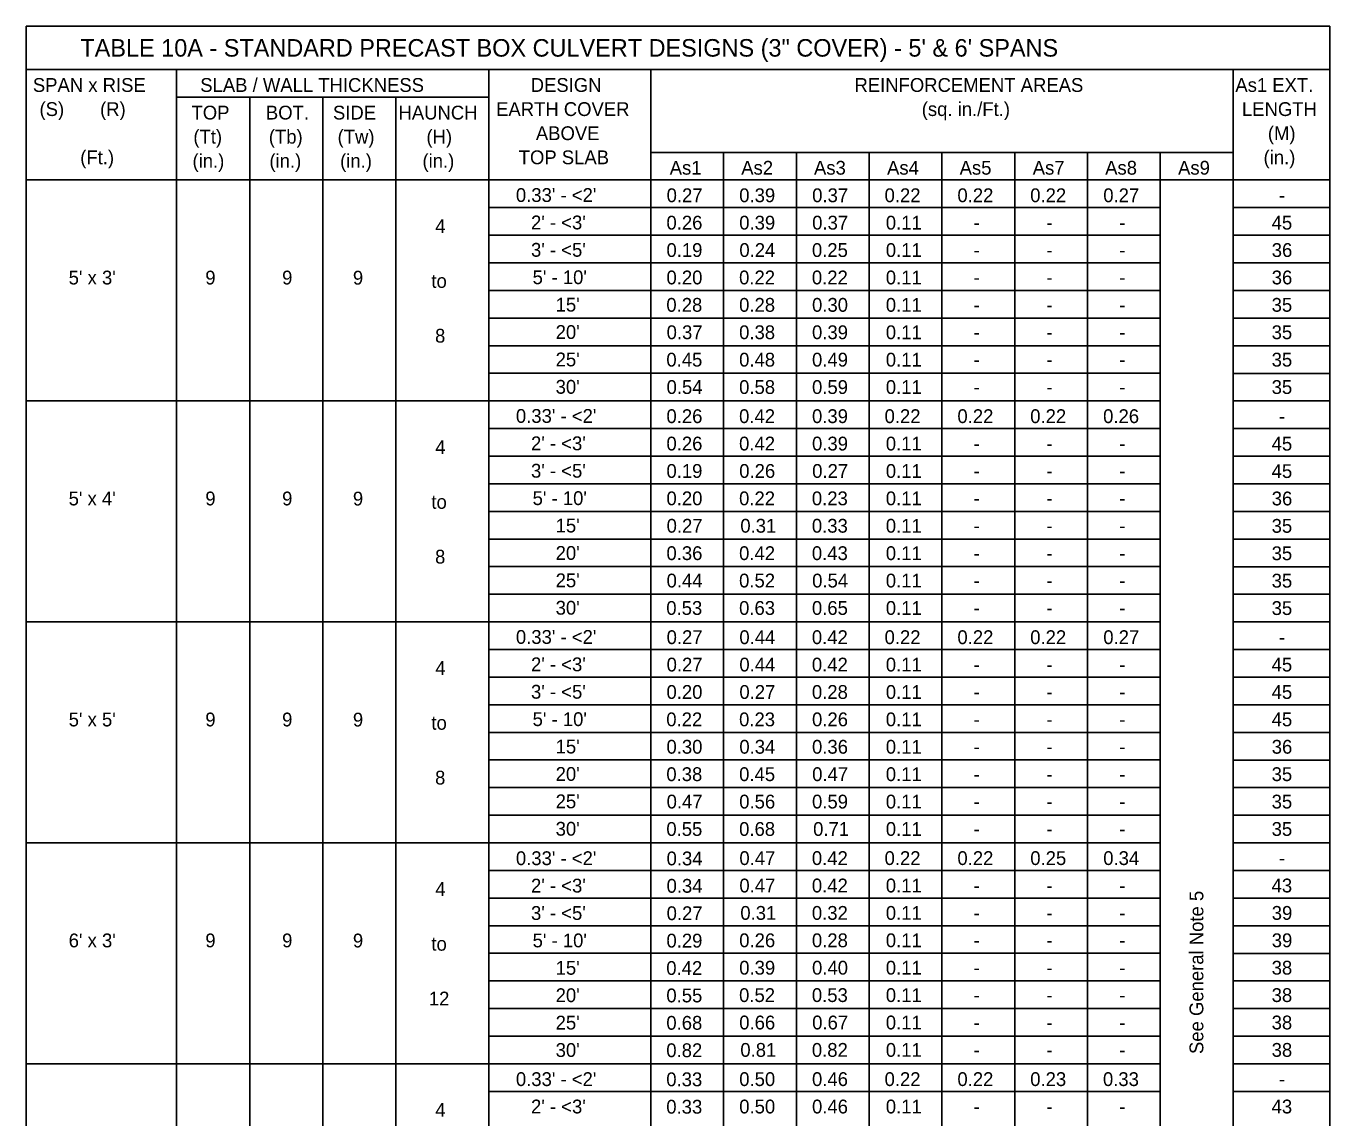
# Model space of a CAD drawing. Extents: x 10338.56 to 10340.78, y 76371.55 to 76372.62.
# Drawn here: x 10338.57 to 10339.164, y 76372.037 to 76372.535 of the extents above; entities that cross this region are included whole.
import ezdxf

# ---------------------------------------------------------------- set-up
doc = ezdxf.new("R2010")
doc.units = 0
doc.layers.add('AdhocPoint_dp', color=7, linetype='Continuous')
doc.layers.add('PlotBorder_dp', color=7, linetype='Continuous')

msp = doc.modelspace()

# ---------------------------------------------------------------- linework, layer by layer
at = {"layer": 'PlotBorder_dp'}
for p, q in [((10338.5697, 76372.53475), (10338.5697, 76371.75893)), ((10338.5697, 76372.53475), (10339.16444, 76372.53475)), ((10339.16444, 76372.53475), (10339.16444, 76371.75893)), ((10338.5697, 76372.51488), (10339.16444, 76372.51488)), ((10338.63833, 76372.51488), (10338.63833, 76371.75893)), ((10338.78078, 76372.51488), (10338.78078, 76371.75893)), ((10338.85466, 76372.51488), (10338.85466, 76371.75893)), ((10339.12025, 76372.51488), (10339.12025, 76371.75893)), ((10338.63833, 76372.50228), (10338.78078, 76372.50228)), ((10338.67169, 76372.50228), (10338.67169, 76371.75893)), ((10338.70506, 76372.50228), (10338.70506, 76371.75893)), ((10338.73842, 76372.50228), (10338.73842, 76371.75893)), ((10338.85466, 76372.47713), (10339.12025, 76372.47713)), ((10338.88786, 76372.47713), (10338.88786, 76371.75893)), ((10338.92106, 76372.47713), (10338.92106, 76371.75893)), ((10338.95425, 76372.47713), (10338.95425, 76371.75893)), ((10338.98745, 76372.47713), (10338.98745, 76371.75893)), ((10339.02065, 76372.47713), (10339.02065, 76371.75893)), ((10339.02065, 76372.47713), (10339.02065, 76371.75893)), ((10339.05385, 76372.47713), (10339.05385, 76371.75893)), ((10339.08705, 76372.47713), (10339.08705, 76371.75893)), ((10338.5697, 76372.46453), (10339.16444, 76372.46453)), ((10338.78078, 76372.45193), (10339.08705, 76372.45193)), ((10339.12025, 76372.45191), (10339.16444, 76372.45191)), ((10338.78078, 76372.43933), (10339.08705, 76372.43933)), ((10339.12025, 76372.43931), (10339.16444, 76372.43931)), ((10338.78078, 76372.42673), (10339.08705, 76372.42673)), ((10339.12025, 76372.42671), (10339.16444, 76372.42671)), ((10338.78078, 76372.41413), (10339.08705, 76372.41413)), ((10339.12025, 76372.41411), (10339.16444, 76372.41411)), ((10338.78078, 76372.40153), (10339.08705, 76372.40153)), ((10339.12025, 76372.40151), (10339.16444, 76372.40151)), ((10338.78078, 76372.38893), (10339.08705, 76372.38893)), ((10339.12025, 76372.38891), (10339.16444, 76372.38891)), ((10338.78078, 76372.37633), (10339.08705, 76372.37633)), ((10339.12025, 76372.37631), (10339.16444, 76372.37631)), ((10338.5697, 76372.36373), (10339.08705, 76372.36373)), ((10339.12025, 76372.36371), (10339.16444, 76372.36371)), ((10338.78078, 76372.35113), (10339.08705, 76372.35113)), ((10339.12025, 76372.35111), (10339.16444, 76372.35111)), ((10338.78078, 76372.33853), (10339.08705, 76372.33853)), ((10339.12025, 76372.33851), (10339.16444, 76372.33851)), ((10338.78078, 76372.32593), (10339.08705, 76372.32593)), ((10339.12025, 76372.32591), (10339.16444, 76372.32591)), ((10338.78078, 76372.31333), (10339.08705, 76372.31333)), ((10339.12025, 76372.31331), (10339.16444, 76372.31331)), ((10338.78078, 76372.30073), (10339.08705, 76372.30073)), ((10339.12025, 76372.30071), (10339.16444, 76372.30071)), ((10338.78078, 76372.28813), (10339.08705, 76372.28813)), ((10339.12025, 76372.28811), (10339.16444, 76372.28811)), ((10338.78078, 76372.27553), (10339.08705, 76372.27553)), ((10339.12025, 76372.27551), (10339.16444, 76372.27551)), ((10338.5697, 76372.26293), (10339.08705, 76372.26293)), ((10339.12025, 76372.26291), (10339.16444, 76372.26291)), ((10338.78078, 76372.25033), (10339.08705, 76372.25033)), ((10339.12025, 76372.25031), (10339.16444, 76372.25031)), ((10338.78078, 76372.23773), (10339.08705, 76372.23773)), ((10339.12025, 76372.23771), (10339.16444, 76372.23771)), ((10338.78078, 76372.22513), (10339.08705, 76372.22513)), ((10339.12025, 76372.22511), (10339.16444, 76372.22511)), ((10338.78078, 76372.21253), (10339.08705, 76372.21253)), ((10339.12025, 76372.21251), (10339.16444, 76372.21251)), ((10338.78078, 76372.19993), (10339.08705, 76372.19993)), ((10339.12025, 76372.19991), (10339.16444, 76372.19991)), ((10338.78078, 76372.18733), (10339.08705, 76372.18733)), ((10339.12025, 76372.18731), (10339.16444, 76372.18731)), ((10338.78078, 76372.17473), (10339.08705, 76372.17473)), ((10339.12025, 76372.17471), (10339.16444, 76372.17471)), ((10338.5697, 76372.16213), (10339.08705, 76372.16213)), ((10339.12025, 76372.16211), (10339.16444, 76372.16211)), ((10338.78078, 76372.14953), (10339.08705, 76372.14953)), ((10339.12025, 76372.14951), (10339.16444, 76372.14951)), ((10338.78078, 76372.13693), (10339.08705, 76372.13693)), ((10339.12025, 76372.13691), (10339.16444, 76372.13691)), ((10338.78078, 76372.12433), (10339.08705, 76372.12433)), ((10339.12025, 76372.12431), (10339.16444, 76372.12431)), ((10338.78078, 76372.11173), (10339.08705, 76372.11173)), ((10339.12025, 76372.11171), (10339.16444, 76372.11171)), ((10338.78078, 76372.09913), (10339.08705, 76372.09913)), ((10339.12025, 76372.09911), (10339.16444, 76372.09911)), ((10338.78078, 76372.08653), (10339.08705, 76372.08653)), ((10339.12025, 76372.08651), (10339.16444, 76372.08651)), ((10338.78078, 76372.07393), (10339.08705, 76372.07393)), ((10339.12025, 76372.07391), (10339.16444, 76372.07391)), ((10338.5697, 76372.06133), (10339.08705, 76372.06133)), ((10338.78139, 76372.06131), (10338.85356, 76372.06131)), ((10339.12025, 76372.06131), (10339.16444, 76372.06131)), ((10338.78078, 76372.04873), (10339.08705, 76372.04873)), ((10339.12025, 76372.04871), (10339.16444, 76372.04871))]:
    msp.add_line(p, q, dxfattribs=at)

# ---------------------------------------------------------------- texts
at = {"layer": 'AdhocPoint_dp'}
for s, height, p in [('TABLE 10A - STANDARD PRECAST BOX CULVERT DESIGNS (3" COVER) - 5\' & 6\' SPANS', 0.008, (10338.59446, 76372.52081)), ('SLAB / WALL THICKNESS', 0.0063, (10338.64915, 76372.50472)), ('As1', 0.0063, (10338.86328, 76372.46696)), ('As2', 0.0063, (10338.89591, 76372.46696)), ('As3', 0.0063, (10338.9291, 76372.46696)), ('As4', 0.0063, (10338.96243, 76372.46696)), ('As5', 0.0063, (10338.99553, 76372.46696)), ('As7', 0.0063, (10339.02887, 76372.46696)), ('As8', 0.0063, (10339.06192, 76372.46696)), ('As9', 0.0063, (10339.09517, 76372.46696)), ("5' x 3'", 0.0063, (10338.58912, 76372.41686)), ('9', 0.0063, (10338.65145, 76372.41686)), ('9', 0.0063, (10338.68649, 76372.41686)), ('9', 0.0063, (10338.71878, 76372.4168)), ("5' x 4'", 0.0063, (10338.58911, 76372.31607)), ('9', 0.0063, (10338.65145, 76372.31607)), ('9', 0.0063, (10338.68649, 76372.31607)), ('9', 0.0063, (10338.71878, 76372.31602)), ("5' x 5'", 0.0063, (10338.58913, 76372.21524)), ('9', 0.0063, (10338.65145, 76372.21524)), ('9', 0.0063, (10338.68649, 76372.21524)), ('9', 0.0063, (10338.71878, 76372.21519)), ('9', 0.0063, (10338.65145, 76372.11446)), ('9', 0.0063, (10338.68649, 76372.11446)), ('9', 0.0063, (10338.71878, 76372.11441))]:
    msp.add_text(s, height=height, dxfattribs=at).set_placement(p)
msp.add_text('See General Note 5', height=0.0063, rotation=90, dxfattribs=at).set_placement((10339.1067, 76372.06579))
at = {"layer": 'PlotBorder_dp'}
for s, p in [('SPAN x RISE', (10338.57279, 76372.50472)), ('DESIGN', (10338.79988, 76372.50472)), ('REINFORCEMENT AREAS', (10338.94756, 76372.50472)), ('(S)       (R)', (10338.57583, 76372.49372)), ('TOP', (10338.64516, 76372.49212)), ('BOT.', (10338.67909, 76372.49212)), ('SIDE', (10338.70968, 76372.49212)), ('HAUNCH', (10338.73958, 76372.49212)), ('EARTH COVER', (10338.78409, 76372.49372)), ('(sq. in./Ft.)', (10338.97825, 76372.49372)), ('ABOVE', (10338.80223, 76372.48272)), ('(Tt)', (10338.646, 76372.48112)), ('(Tb)', (10338.68043, 76372.48112)), ('(Tw)', (10338.71179, 76372.48112)), ('(H)', (10338.75232, 76372.48112)), ('(Ft.)', (10338.5944, 76372.47172)), ('(in.)', (10338.64561, 76372.47012)), ('(in.)', (10338.6807, 76372.47012)), ('(in.)', (10338.71294, 76372.47012)), ('(in.)', (10338.75051, 76372.47012)), ('TOP SLAB', (10338.7944, 76372.47172)), ("0.33' - <2'", (10338.79313, 76372.45451)), ('0.27', (10338.86188, 76372.45441)), ('0.39', (10338.895, 76372.45441)), ('0.37', (10338.92827, 76372.45441)), ('0.22', (10338.96129, 76372.45441)), ('0.22', (10338.99452, 76372.45441)), ('0.22', (10339.02773, 76372.45441)), ('0.27', (10339.06106, 76372.45441)), ('-', (10339.14117, 76372.45441)), ("2' - <3'", (10338.80003, 76372.44201)), ('0.26', (10338.8618, 76372.44191)), ('0.39', (10338.895, 76372.44191)), ('0.37', (10338.92827, 76372.44191)), ('0.11', (10338.96186, 76372.44191)), ('45', (10339.13786, 76372.44191)), ('4', (10338.75636, 76372.44033)), ('-', (10339.00192, 76372.44191)), ('-', (10339.03513, 76372.44191)), ('-', (10339.06832, 76372.44191)), ("3' - <5'", (10338.80003, 76372.42951)), ('0.19', (10338.8618, 76372.42941)), ('0.24', (10338.89506, 76372.42941)), ('0.25', (10338.92816, 76372.42941)), ('0.11', (10338.96186, 76372.42941)), ('36', (10339.1379, 76372.42941)), ('-', (10339.00192, 76372.42941)), ('-', (10339.03513, 76372.42941)), ('-', (10339.06832, 76372.42941)), ("5' - 10'", (10338.80075, 76372.41701)), ('0.20', (10338.86181, 76372.41691)), ('0.22', (10338.89493, 76372.41691)), ('0.22', (10338.92813, 76372.41691)), ('0.11', (10338.96186, 76372.41691)), ('36', (10339.1379, 76372.41691)), ('to', (10338.75458, 76372.41533)), ('-', (10339.00192, 76372.41691)), ('-', (10339.03513, 76372.41691)), ('-', (10339.06832, 76372.41691)), ("15'", (10338.81126, 76372.40451)), ('0.28', (10338.86175, 76372.40441)), ('0.28', (10338.89495, 76372.40441)), ('0.30', (10338.92821, 76372.40441)), ('0.11', (10338.96186, 76372.40441)), ('-', (10339.00192, 76372.40441)), ('-', (10339.03513, 76372.40441)), ('-', (10339.06832, 76372.40441)), ('35', (10339.13786, 76372.40441)), ('8', (10338.75625, 76372.39033)), ("20'", (10338.81126, 76372.39201)), ('0.37', (10338.86188, 76372.39191)), ('0.38', (10338.89495, 76372.39191)), ('0.39', (10338.9282, 76372.39191)), ('0.11', (10338.96186, 76372.39191)), ('-', (10339.00192, 76372.39191)), ('-', (10339.03513, 76372.39191)), ('-', (10339.06832, 76372.39191)), ('35', (10339.13786, 76372.39191)), ("25'", (10338.81126, 76372.37951)), ('0.45', (10338.86176, 76372.37941)), ('0.48', (10338.89495, 76372.37941)), ('0.49', (10338.9282, 76372.37941)), ('0.11', (10338.96186, 76372.37941)), ('-', (10339.00192, 76372.37941)), ('-', (10339.03513, 76372.37941)), ('-', (10339.06832, 76372.37941)), ('35', (10339.13786, 76372.37941)), ("30'", (10338.81126, 76372.36701)), ('0.54', (10338.86186, 76372.36691)), ('0.58', (10338.89495, 76372.36691)), ('0.59', (10338.9282, 76372.36691)), ('0.11', (10338.96186, 76372.36691)), ('-', (10339.00192, 76372.36691)), ('-', (10339.03513, 76372.36691)), ('-', (10339.06832, 76372.36691)), ('35', (10339.13786, 76372.36691)), ("0.33' - <2'", (10338.79313, 76372.35373)), ('0.26', (10338.8618, 76372.35363)), ('0.42', (10338.89493, 76372.35363)), ('0.39', (10338.9282, 76372.35363)), ('0.22', (10338.96129, 76372.35363)), ('0.22', (10338.99452, 76372.35363)), ('0.22', (10339.02773, 76372.35363)), ('0.26', (10339.06098, 76372.35363)), ('-', (10339.14117, 76372.35358)), ("2' - <3'", (10338.80003, 76372.34123)), ('0.26', (10338.8618, 76372.34113)), ('0.42', (10338.89493, 76372.34113)), ('0.39', (10338.9282, 76372.34113)), ('0.11', (10338.96186, 76372.34113)), ('45', (10339.13786, 76372.34108)), ('4', (10338.75636, 76372.33953)), ('-', (10339.00192, 76372.34113)), ('-', (10339.03513, 76372.34113)), ('-', (10339.06832, 76372.34113)), ("3' - <5'", (10338.80003, 76372.32873)), ('0.19', (10338.8618, 76372.32863)), ('0.26', (10338.895, 76372.32863)), ('0.27', (10338.92827, 76372.32863)), ('0.11', (10338.96186, 76372.32863)), ('45', (10339.13786, 76372.32858)), ('-', (10339.00192, 76372.32863)), ('-', (10339.03513, 76372.32863)), ('-', (10339.06832, 76372.32863)), ("5' - 10'", (10338.80075, 76372.31623)), ('0.20', (10338.86181, 76372.31613)), ('0.22', (10338.89493, 76372.31613)), ('0.23', (10338.92813, 76372.31613)), ('0.11', (10338.96186, 76372.31613)), ('36', (10339.1379, 76372.31608)), ('to', (10338.75458, 76372.31453)), ('-', (10339.00192, 76372.31613)), ('-', (10339.03513, 76372.31613)), ('-', (10339.06832, 76372.31613)), ("15'", (10338.81126, 76372.30373)), ('0.27', (10338.86188, 76372.30363)), ('0.31', (10338.8955, 76372.30363)), ('0.33', (10338.92813, 76372.30363)), ('0.11', (10338.96186, 76372.30363)), ('-', (10339.00192, 76372.30363)), ('-', (10339.03513, 76372.30363)), ('-', (10339.06832, 76372.30363)), ('35', (10339.13786, 76372.30358)), ('8', (10338.75625, 76372.28953)), ("20'", (10338.81126, 76372.29123)), ('0.36', (10338.8618, 76372.29113)), ('0.42', (10338.89493, 76372.29113)), ('0.43', (10338.92813, 76372.29113)), ('0.11', (10338.96186, 76372.29113)), ('-', (10339.00192, 76372.29113)), ('-', (10339.03513, 76372.29113)), ('-', (10339.06832, 76372.29113)), ('35', (10339.13786, 76372.29108)), ("25'", (10338.81126, 76372.27873)), ('0.44', (10338.86186, 76372.27863)), ('0.52', (10338.89493, 76372.27863)), ('0.54', (10338.92826, 76372.27863)), ('0.11', (10338.96186, 76372.27863)), ('-', (10339.00192, 76372.27863)), ('-', (10339.03513, 76372.27863)), ('-', (10339.06832, 76372.27863)), ('35', (10339.13786, 76372.27858)), ("30'", (10338.81126, 76372.26623)), ('0.53', (10338.86173, 76372.26613)), ('0.63', (10338.89493, 76372.26613)), ('0.65', (10338.92816, 76372.26613)), ('0.11', (10338.96186, 76372.26613)), ('-', (10339.00192, 76372.26613)), ('-', (10339.03513, 76372.26613)), ('-', (10339.06832, 76372.26613)), ('35', (10339.13786, 76372.26608)), ("0.33' - <2'", (10338.79313, 76372.2529)), ('0.27', (10338.86188, 76372.2528)), ('0.44', (10338.89506, 76372.2528)), ('0.42', (10338.92813, 76372.2528)), ('0.22', (10338.96129, 76372.2528)), ('0.22', (10338.99452, 76372.2528)), ('0.22', (10339.02773, 76372.2528)), ('0.27', (10339.06106, 76372.2528)), ('-', (10339.14117, 76372.2528)), ('4', (10338.75636, 76372.23873)), ("2' - <3'", (10338.80003, 76372.2404)), ('0.27', (10338.86188, 76372.2403)), ('0.44', (10338.89506, 76372.2403)), ('0.42', (10338.92813, 76372.2403)), ('0.11', (10338.96186, 76372.2403)), ('45', (10339.13786, 76372.2403)), ('-', (10339.00192, 76372.2403)), ('-', (10339.03513, 76372.2403)), ('-', (10339.06832, 76372.2403)), ("3' - <5'", (10338.80003, 76372.2279)), ('0.20', (10338.86181, 76372.2278)), ('0.27', (10338.89507, 76372.2278)), ('0.28', (10338.92815, 76372.2278)), ('0.11', (10338.96186, 76372.2278)), ('45', (10339.13786, 76372.2278)), ('-', (10339.00192, 76372.2278)), ('-', (10339.03513, 76372.2278)), ('-', (10339.06832, 76372.2278)), ("5' - 10'", (10338.80075, 76372.2154)), ('0.22', (10338.86173, 76372.2153)), ('0.23', (10338.89493, 76372.2153)), ('0.26', (10338.9282, 76372.2153)), ('0.11', (10338.96186, 76372.2153)), ('45', (10339.13786, 76372.2153)), ('to', (10338.75458, 76372.21373)), ('-', (10339.00192, 76372.2153)), ('-', (10339.03513, 76372.2153)), ('-', (10339.06832, 76372.2153)), ("15'", (10338.81126, 76372.2029)), ('0.30', (10338.86181, 76372.2028)), ('0.34', (10338.89506, 76372.2028)), ('0.36', (10338.9282, 76372.2028)), ('0.11', (10338.96186, 76372.2028)), ('36', (10339.1379, 76372.2028)), ('-', (10339.00192, 76372.2028)), ('-', (10339.03513, 76372.2028)), ('-', (10339.06832, 76372.2028)), ('8', (10338.75625, 76372.18873)), ("20'", (10338.81126, 76372.1904)), ('0.38', (10338.86175, 76372.1903)), ('0.45', (10338.89496, 76372.1903)), ('0.47', (10338.92827, 76372.1903)), ('0.11', (10338.96186, 76372.1903)), ('-', (10339.00192, 76372.1903)), ('-', (10339.03513, 76372.1903)), ('-', (10339.06832, 76372.1903)), ('35', (10339.13786, 76372.1903)), ("25'", (10338.81126, 76372.1779)), ('0.47', (10338.86188, 76372.1778)), ('0.56', (10338.895, 76372.1778)), ('0.59', (10338.9282, 76372.1778)), ('0.11', (10338.96186, 76372.1778)), ('-', (10339.00192, 76372.1778)), ('-', (10339.03513, 76372.1778)), ('-', (10339.06832, 76372.1778)), ('35', (10339.13786, 76372.1778)), ("30'", (10338.81126, 76372.1654)), ('0.55', (10338.86176, 76372.1653)), ('0.68', (10338.89495, 76372.1653)), ('0.71', (10338.9287, 76372.1653)), ('0.11', (10338.96186, 76372.1653)), ('-', (10339.00192, 76372.1653)), ('-', (10339.03513, 76372.1653)), ('-', (10339.06832, 76372.1653)), ('35', (10339.13786, 76372.1653)), ("0.33' - <2'", (10338.79313, 76372.15196)), ('0.34', (10338.86186, 76372.15186)), ('0.47', (10338.89507, 76372.15201)), ('0.42', (10338.92813, 76372.15201)), ('0.22', (10338.96129, 76372.15201)), ('0.22', (10338.99452, 76372.15201)), ('0.25', (10339.02776, 76372.15201)), ('0.34', (10339.06104, 76372.15201)), ('-', (10339.14117, 76372.15201)), ('4', (10338.75636, 76372.13793)), ("2' - <3'", (10338.80003, 76372.13946)), ('0.34', (10338.86186, 76372.13936)), ('0.47', (10338.89507, 76372.13951)), ('0.42', (10338.92813, 76372.13951)), ('0.11', (10338.96186, 76372.13951)), ('43', (10339.13783, 76372.13951)), ('-', (10339.00192, 76372.13951)), ('-', (10339.03513, 76372.13951)), ('-', (10339.06832, 76372.13951)), ("3' - <5'", (10338.80003, 76372.12696)), ('0.27', (10338.86188, 76372.12686)), ('0.31', (10338.8955, 76372.12701)), ('0.32', (10338.92813, 76372.12701)), ('0.11', (10338.96186, 76372.12701)), ('39', (10339.1379, 76372.12701)), ('-', (10339.00192, 76372.12701)), ('-', (10339.03513, 76372.12701)), ('-', (10339.06832, 76372.12701)), ("6' x 3'", (10338.58913, 76372.11446)), ("5' - 10'", (10338.80075, 76372.11446)), ('0.29', (10338.8618, 76372.11436)), ('0.26', (10338.895, 76372.11451)), ('0.28', (10338.92815, 76372.11451)), ('0.11', (10338.96186, 76372.11451)), ('39', (10339.1379, 76372.11451)), ('to', (10338.75458, 76372.11293)), ('-', (10339.00192, 76372.11451)), ('-', (10339.03513, 76372.11451)), ('-', (10339.06832, 76372.11451)), ("15'", (10338.81126, 76372.10196)), ('0.42', (10338.86173, 76372.10186)), ('0.39', (10338.895, 76372.10201)), ('0.40', (10338.92821, 76372.10201)), ('0.11', (10338.96186, 76372.10201)), ('38', (10339.13786, 76372.10201)), ('-', (10339.00192, 76372.10201)), ('-', (10339.03513, 76372.10201)), ('-', (10339.06832, 76372.10201)), ('12', (10338.7534, 76372.08793)), ("20'", (10338.81126, 76372.08946)), ('0.55', (10338.86176, 76372.08936)), ('0.52', (10338.89493, 76372.08951)), ('0.53', (10338.92813, 76372.08951)), ('0.11', (10338.96186, 76372.08951)), ('-', (10339.00192, 76372.08951)), ('-', (10339.03513, 76372.08951)), ('-', (10339.06832, 76372.08951)), ('38', (10339.13786, 76372.08951)), ("25'", (10338.81126, 76372.07696)), ('0.68', (10338.86175, 76372.07686)), ('0.66', (10338.895, 76372.07701)), ('0.67', (10338.92827, 76372.07701)), ('0.11', (10338.96186, 76372.07701)), ('-', (10339.00192, 76372.07701)), ('-', (10339.03513, 76372.07701)), ('-', (10339.06832, 76372.07701)), ('38', (10339.13786, 76372.07701)), ("30'", (10338.81126, 76372.06446)), ('0.82', (10338.86173, 76372.06436)), ('0.81', (10338.8955, 76372.06451)), ('0.82', (10338.92813, 76372.06451)), ('0.11', (10338.96186, 76372.06451)), ('-', (10339.00192, 76372.06451)), ('-', (10339.03513, 76372.06451)), ('-', (10339.06832, 76372.06451)), ('38', (10339.13786, 76372.06451)), ("0.33' - <2'", (10338.79313, 76372.05118)), ('0.33', (10338.86173, 76372.05108)), ('0.50', (10338.89501, 76372.05118)), ('0.46', (10338.9282, 76372.05118)), ('0.22', (10338.96129, 76372.05118)), ('0.22', (10338.99452, 76372.05118)), ('0.23', (10339.02773, 76372.05118)), ('0.33', (10339.06091, 76372.05118)), ('-', (10339.14117, 76372.05118)), ('4', (10338.75636, 76372.03713)), ("2' - <3'", (10338.80003, 76372.03868)), ('0.33', (10338.86173, 76372.03858)), ('0.50', (10338.89501, 76372.03868)), ('0.46', (10338.9282, 76372.03868)), ('0.11', (10338.96186, 76372.03868)), ('43', (10339.13783, 76372.03868)), ('-', (10339.00192, 76372.03868)), ('-', (10339.03513, 76372.03868)), ('-', (10339.06832, 76372.03868))]:
    msp.add_text(s, height=0.0063, dxfattribs=at).set_placement(p)
for s, p in [('As1 EXT.', (10339.12129, 76372.50472)), ('LENGTH', (10339.12432, 76372.49372)), ('(M)', (10339.13613, 76372.48272)), ('(in.)', (10339.13416, 76372.47172))]:
    msp.add_text(s, height=0.0063, rotation=360, dxfattribs=at).set_placement(p)

doc.saveas('drawing.dxf')
